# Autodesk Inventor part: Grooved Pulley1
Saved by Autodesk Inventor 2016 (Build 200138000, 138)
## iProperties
Created: 2015-03
Part Number: Grooved Pulley1
Material: Steel
Document SubType Name: Modeling
Designer: Uglješa
Density: 1 g/cm^3
Appearance: Steel
CustomPartVersion: 1
Author: Uglješa
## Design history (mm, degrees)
sketch "Main Sketch"
  geometry: L1 (0, 76)-(42, 76); L2 (42, 76)-(42, 12.861); L3 (42, 12.861)-(31, 9.498); L4 (31, 9.498)-(31, 6.502); L5 (31, 6.502)-(42, 3.139); L6 (42, 3.139)-(42, 0); L7 (42, 0)-(0, 0); L8 (40, 12.25)-(40, 3.75); L9 (31, 8)-(40, 8); L10 (42, 12.861)-(42, 3.139); L11 (0, -4)-(0, 24) reference; L12 (0, 0)-(0, 76)
  constraints: 22 end point, 5 perpendicular, 2 collinear, 2 midpoint, 2 point on line, 1 parallel
  dimensions: "d0" = 8.5 distance of L8.start L8.end (= da_Bw); "d1" = 34 deg angle of L3 L5 (= da_Alfa); "d2" = 2 distance between parallel lines of L2 L8 (= da_c); "d6" = 76 distance between parallel lines of L7 L1 (computed from d5, da_ng, da_Sg); "d21" = 80 diameter of L8 L11 (= da_Dw); "d25" = 11 distance between parallel lines of L4 L10 (= da_Hd); "d27" = 8 distance between parallel lines of L7 L9 (= da_Se)
node "Belt Plane"
revolve "Body" stored, may be unused: angle "d7" = 90 deg
revolve "Groove" stored, may be unused: angle "d15" = 90 deg
fillet "Fillet External" dims "d8" = 0 (computed from da_r1), "d10" = 0, "da_r1" = 0 [user parameter; used in 1 equation term]
fillet "Fillet Internal" dims "d9" = 0 (computed from da_r2), "d11" = 0, "da_r2" = 0 [user parameter; used in 1 equation term]
pattern_linear "Groove Pattern" dims "d18" = 12 (= da_Sg)
body "Solid1"
other parameters: "d5" = 8 (= da_Se), "da_Bw" = 8.5 [user parameter; used in 1 equation term], "da_Alfa" = 34 deg [user parameter; used in 1 equation term], "da_c" = 2 [user parameter; used in 1 equation term], "da_Dw" = 80 [user parameter; used in 1 equation term], "da_Hd" = 11 [user parameter; used in 1 equation term], "da_Se" = 8 [user parameter; used in 2 equation terms], "da_Sg" = 12 [user parameter; used in 2 equation terms], "d24" = 0, "d26" = 0
